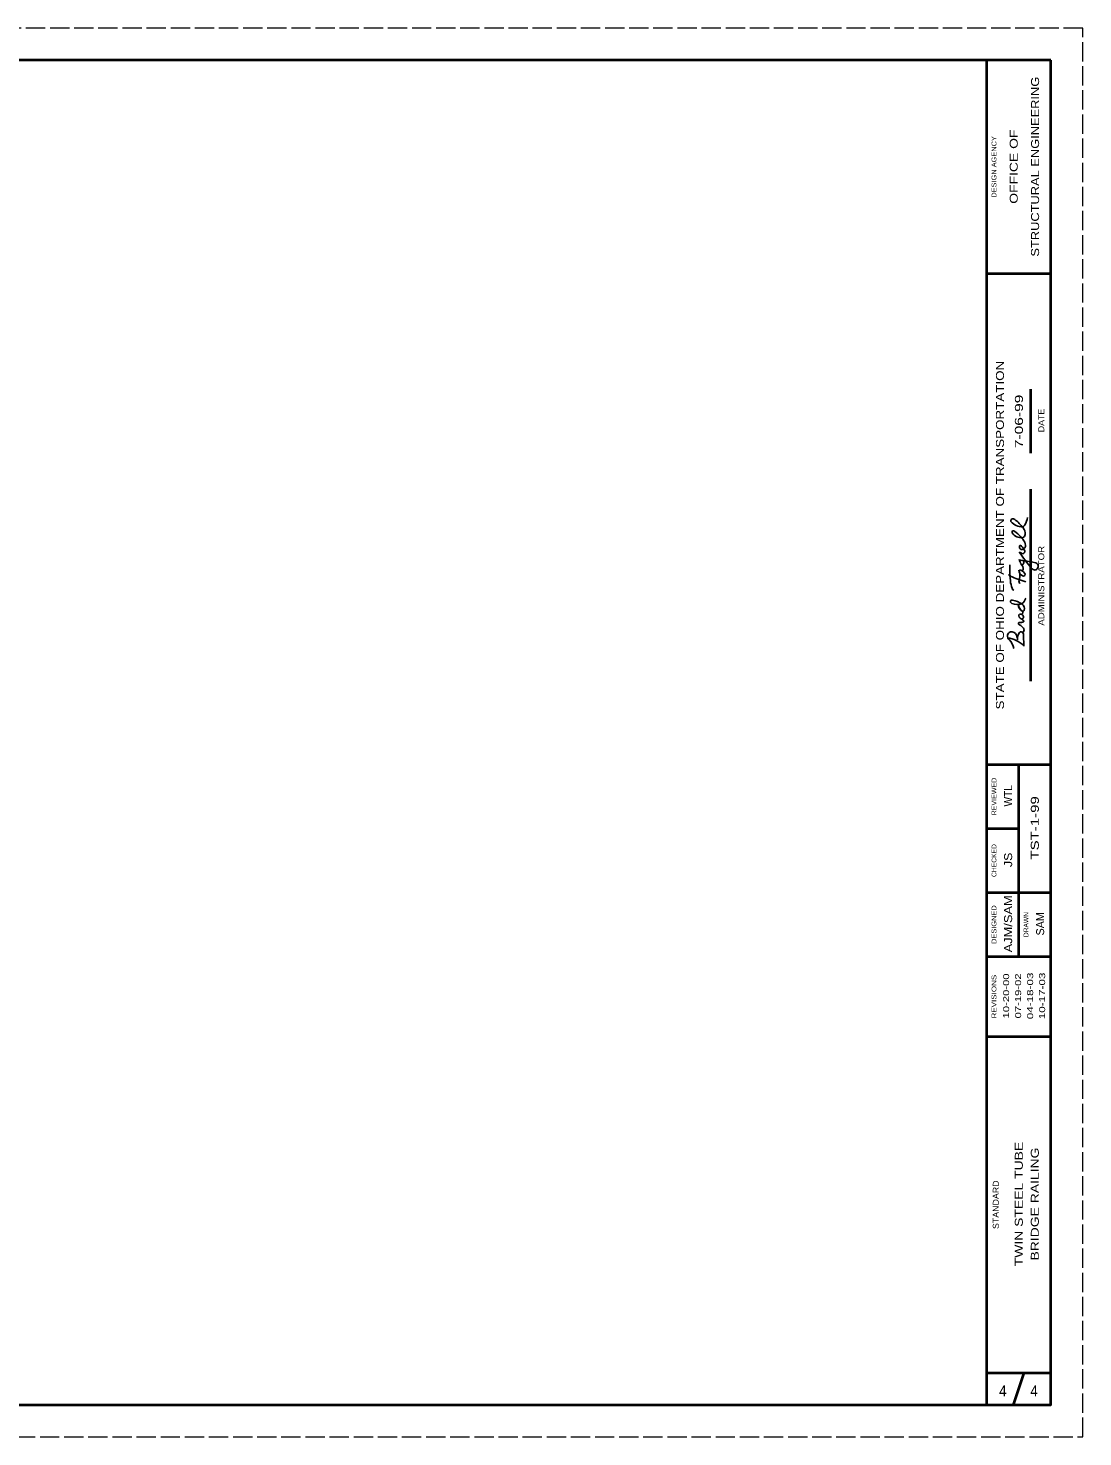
# Model space of a CAD drawing. Extents: x 1285 to 1427, y 1365 to 1427.
# Drawn here: x 1404.7 to 1426.67, y 1365.33 to 1394.67 of the extents above; entities that cross this region are included whole.
import ezdxf
from ezdxf.enums import TextEntityAlignment as Align

# ---------------------------------------------------------------- set-up
doc = ezdxf.new("R2010")
doc.units = 0
doc.header["$LTSCALE"] = 0.067
doc.linetypes.add('LONG_DASHED', pattern=[7.5, 6, -1.5])
for name, color, linetype, lineweight in [('1', 7, 'Continuous', 40), ('43', 7, 'Continuous', 25), ('44', 7, 'Continuous', 13)]:
    doc.layers.add(name, color=color, linetype=linetype, lineweight=lineweight)
doc.layers.add('41', color=7, linetype='Continuous')

msp = doc.modelspace()

# ---------------------------------------------------------------- linework, layer by layer
at = {"layer": '1'}
for p, q in [((1424.66667, 1366), (1424.66667, 1394)), ((1424.66667, 1389.55556), (1426, 1389.55556)), ((1425.58544, 1385.81722), (1425.58544, 1387.15056)), ((1425.58544, 1381.06933), (1425.58544, 1385.06933)), ((1424.66667, 1379.33333), (1426, 1379.33333)), ((1425.33333, 1375.33333), (1425.33333, 1379.33333)), ((1424.66667, 1378), (1425.33333, 1378)), ((1424.66667, 1376.66667), (1426, 1376.66667)), ((1424.66667, 1375.33333), (1426, 1375.33333)), ((1424.66667, 1373.66667), (1426, 1373.66667)), ((1424.66667, 1366.66667), (1426, 1366.66667)), ((1425.22222, 1366), (1425.44444, 1366.66667))]:
    msp.add_line(p, q, dxfattribs=at)
at = {"layer": '1', "linetype": 'LONG_DASHED', "lineweight": 13}
msp.add_lwpolyline([(1426.66667, 1394.66667), (1381.33333, 1394.66667), (1381.33333, 1365.33333), (1426.66667, 1365.33333)], close=True, dxfattribs=at)
at = {"layer": '1'}
msp.add_lwpolyline([(1426, 1394), (1384, 1394), (1384, 1366), (1426, 1366)], close=True, dxfattribs=at)
at = {"layer": '43'}
for p, q in [((1425.58544, 1381.06933), (1425.58544, 1385.06933)), ((1425.34789, 1383.10722), (1425.35878, 1383.111)), ((1425.43356, 1382.03556), (1425.43789, 1381.79789))]:
    msp.add_line(p, q, dxfattribs=at)
for centre, radius, start, end in [((1425.21212, 1384.40995), 0.0444, 113.98019, 198.40352), ((1425.40091, 1384.57947), 0.29498, 218.47768, 273.26047), ((1425.20855, 1384.39627), 0.05616, 45.85596, 104.94474), ((1424.8206, 1383.84326), 0.73103, 34.63262, 54.25344), ((1425.39668, 1384.34987), 0.06821, 287.93982, 338.66307), ((1425.30517, 1384.14954), 0.15997, 350.92499, 43.03504), ((1425.12137, 1384.52764), 0.39479, 329.12441, 352.69329), ((1425.22172, 1384.17314), 0.02998, 124.49102, 212.28704), ((1425.38173, 1384.27434), 0.21931, 212.30855, 277.889), ((1425.21397, 1384.14582), 0.05284, 48.28094, 100.06036), ((1424.86837, 1383.62818), 0.67478, 29.47671, 55.64687), ((1425.40249, 1384.11742), 0.06104, 278.80614, 6.47651), ((1425.36388, 1383.89986), 0.10996, 328.86402, 33.28654), ((1428.38224, 1385.77289), 3.64497, 213.54695, 220.08659), ((1425.50594, 1384.00132), 0.29155, 236.35413, 252.38173), ((1425.39522, 1383.86332), 0.05046, 134.5839, 276.21021), ((1425.25127, 1383.71199), 0.21645, 24.97701, 59.9081), ((1425.39771, 1383.88883), 0.07573, 272.24638, 322.76314), ((1425.4102, 1383.77175), 0.04888, 278.82355, 40.31415), ((1427.98842, 1383.43924), 2.84328, 179.00808, 186.45308), ((1425.49387, 1383.40728), 0.16551, 190.08126, 239.27146), ((1424.98629, 1383.21951), 0.37945, 13.60485, 24.73867), ((1425.5934, 1383.65823), 0.2578, 191.93662, 216.93201), ((1425.54779, 1384.28376), 0.71555, 253.73211, 261.66584), ((1425.3284, 1383.24507), 0.14238, 31.60989, 82.17754), ((1425.26411, 1383.39941), 0.16158, 356.67266, 44.91278), ((1425.3993, 1383.39972), 0.02786, 240.6235, 339.64142), ((1425.40462, 1383.51462), 0.02065, 213.1438, 334.3378), ((1425.37611, 1383.5457), 0.06182, 319.65709, 31.03704), ((1425.08284, 1380.93154), 2.66879, 76.85896, 82.22082), ((1425.68427, 1383.49713), 0.11542, 218.20712, 266.08129), ((1425.65938, 1383.45831), 0.0782, 282.55689, 67.28157), ((1425.15742, 1383.28181), 0.02714, 153.49478, 263.55592), ((1426.68362, 1386.98416), 4.03068, 247.70329, 252.57637), ((1425.7996, 1383.23329), 0.64651, 190.12054, 204.37157), ((1425.46429, 1383.15835), 0.12726, 172.05872, 203.71441), ((1425.00792, 1383.28532), 0.34797, 341.67711, 3.86341), ((1425.42948, 1383.29235), 0.03398, 233.58324, 53.58324), ((1425.15656, 1383.0668), 0.11397, 298.36136, 311.08751), ((1425.32029, 1382.8144), 0.15234, 301.08449, 348.26264), ((1425.44611, 1382.78809), 0.0238, 348.64966, 27.37763), ((1425.19088, 1382.72637), 0.02997, 69.75906, 198.23256), ((1425.21181, 1382.7379), 0.05365, 202.93968, 246.57643), ((1425.12893, 1382.26939), 0.49046, 55.75095, 81.52104), ((1425.46203, 1382.6567), 0.13848, 181.88257, 246.32734), ((1425.53177, 1382.70392), 0.21449, 193.96867, 234.24124), ((1425.37917, 1382.50252), 0.03861, 269.53454, 45.09708), ((1425.31242, 1382.57362), 0.13712, 349.99119, 47.55407), ((1425.41888, 1382.55642), 0.02933, 244.8672, 346.93776), ((1425.35205, 1382.26445), 0.02767, 98.82115, 193.06115), ((1425.19175, 1381.98036), 0.30817, 42.72148, 64.36086), ((1425.41096, 1382.44119), 0.08067, 166.84439, 250.80516), ((1425.36796, 1382.47079), 0.18012, 263.57652, 288.13161), ((1425.36172, 1382.39317), 0.07279, 59.10443, 99.26983), ((1425.39531, 1382.39735), 0.03419, 245.21977, 351.61479), ((1424.8706, 1381.60569), 0.91683, 52.41014, 55.91351), ((1425.37479, 1382.40533), 0.05587, 346.57725, 64.21305), ((1425.36871, 1382.13319), 0.07489, 346.73401, 48.68598), ((1425.42027, 1382.3171), 0.01789, 282.06688, 57.53058), ((1425.19083, 1382.00844), 0.09523, 110.48712, 231.46083), ((1424.98456, 1381.30711), 0.67606, 47.9273, 79.95075), ((1424.83133, 1381.64937), 0.41363, 13.62785, 43.47233), ((1425.17933, 1381.98646), 0.11331, 20.71835, 101.10772), ((1424.7228, 1381.85021), 0.58951, 7.54019, 17.40463), ((1425.53016, 1381.95368), 0.22479, 144.2131, 186.6803), ((1425.38, 1382.05578), 0.04357, 27.88325, 137.63831), ((1425.4038, 1382.12692), 0.03935, 278.12859, 343.88559), ((1425.32668, 1382.0191), 0.10811, 8.73681, 31.85217)]:
    msp.add_arc(centre, radius, start, end, dxfattribs=at)
msp.add_ellipse((1425.3057, 1382.93101), major_axis=(-0.11521, -0.24233), ratio=0.970189, start_param=6.28318531, end_param=7.10295967, dxfattribs=at)

# ---------------------------------------------------------------- texts
at = {"layer": '1'}
for s, height, width, p in [('STRUCTURAL ENGINEERING', 0.1667, 1.2, (1425.75556, 1391.78283)), ('OFFICE OF', 0.1667, 1.3, (1425.31111, 1391.78289)), ('DESIGN AGENCY', 0.1, 1.15, (1424.86667, 1391.77778)), ('STATE OF OHIO DEPARTMENT OF TRANSPORTATION', 0.1667, 1.25, (1425.02433, 1384.11006)), ('DATE', 0.125, 1.1, (1425.86311, 1386.49778)), ('ADMINISTRATOR', 0.125, 1.2, (1425.86311, 1383.05511)), ('REVIEWED', 0.1, 1.1, (1424.86667, 1378.66667)), ('CHECKED', 0.1, 1.05, (1424.86667, 1377.33339)), ('DESIGNED', 0.1, 1.15, (1424.86667, 1376)), ('DRAWN', 0.1, 0.95, (1425.53333, 1376)), ('REVISIONS', 0.1, 1.25, (1424.86667, 1374.50011)), ('STANDARD', 0.125, 1.1, (1424.91667, 1370.16672))]:
    msp.add_text(s, height=height, rotation=90, dxfattribs=dict(at, width=width)).set_placement(p, align=Align.CENTER)
at = {"layer": '41'}
for s, width, p in [('10-20-00', 1.4, (1425.132, 1374.51433)), ('07-19-02', 1.4, (1425.382, 1374.51433)), ('04-18-03', 1.45, (1425.632, 1374.51433)), ('10-17-03', 1.45, (1425.882, 1374.51433))]:
    msp.add_text(s, height=0.125, rotation=90, dxfattribs=dict(at, width=width)).set_placement(p, align=Align.CENTER)
at = {"layer": '44'}
for s, width, p in [('7-06-99', 1.45, (1425.41878, 1386.47789)), ('WTL', 0.95, (1425.19444, 1378.68222)), ('TST-1-99', 1.4, (1425.75, 1378.01428)), ('JS', 1.15, (1425.19444, 1377.34767)), ('AJM/SAM', 1.2, (1425.19444, 1376.0155)), ('TWIN STEEL TUBE', 1.3, (1425.41667, 1370.181)), ('BRIDGE RAILING', 1.3, (1425.75, 1370.18094))]:
    msp.add_text(s, height=0.1667, rotation=90, dxfattribs=dict(at, width=width)).set_placement(p, align=Align.CENTER)
msp.add_text('SAM', height=0.1667, rotation=90, dxfattribs=at).set_placement((1425.86111, 1376.01561), align=Align.CENTER)
at = {"layer": '44', "width": 0.9}
for p in [(1425.002, 1366.17478), (1425.65178, 1366.17478)]:
    msp.add_text('4', height=0.2333, dxfattribs=at).set_placement(p, align=Align.CENTER)

doc.saveas('drawing.dxf')
